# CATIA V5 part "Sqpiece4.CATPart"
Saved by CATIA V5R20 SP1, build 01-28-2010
Part number: Sqpiece4
Publications: "Droite.1", "Plan.1", "Droite.2", "Longueur4"
Bounding box of the stored display mesh (mm): x 0 to 150, y -20 to 20, z 0 to 0
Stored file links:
  C:\Users\RENARD Simon\Documents\Cours IFMA\2ème année\IAO\Sqpiece4.CATPart
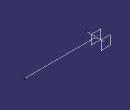
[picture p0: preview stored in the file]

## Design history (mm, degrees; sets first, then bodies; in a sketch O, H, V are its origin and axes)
Parameters
  Longueur4 = 150 mm
Body1 (main body)
  Point1: (0, 0, 0)
  Line1: type PtDir, RefPoint Point1, Direction yz-plane, Start 0, End 150 {= Longueur4}
  Line2: type PtDir, RefPoint Point1, Direction zx-plane, Start -20, End 20
  Plane1: type OffsetPt, RefPlane zx-plane, RefPoint vertex of Line2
